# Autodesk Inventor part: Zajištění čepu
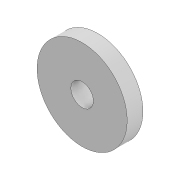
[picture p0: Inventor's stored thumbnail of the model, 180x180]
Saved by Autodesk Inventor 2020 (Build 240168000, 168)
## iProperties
Created: 2025-03
Part Number: Zajištění čepu
Material: Všeobecné
Document SubType Name: Modeling
Designer: doma
Density: 1 g/cm^3
Appearance: Výchozí
Mass: 8.24668 g
Surface Area: 34.5575 cm^2
Volume: 8.24668 cm^3
Author: doma
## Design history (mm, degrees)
sketch "Náčrt1"
  geometry: C1 r 20 at (0, 0); C2 r 5 at (0, 0); 1 further point
  constraints: 2 centre point, 2 coincident
  dimensions: "d0" = 10 diameter of C2; "d1" = 40 diameter of C1
extrude "Vysunutí1" new body sketch "Náčrt1" distance "d2" = 7; taper "d3" = 0 deg
node "Těleso1"
